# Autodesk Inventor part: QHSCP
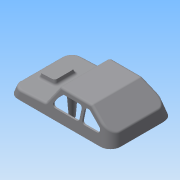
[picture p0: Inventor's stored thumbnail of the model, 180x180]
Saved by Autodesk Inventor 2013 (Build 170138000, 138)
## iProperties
Created: 2015-05
Part Number: QHSCP
Material: 일반
Document SubType Name: Modeling
Designer: WINDOWS7
Density: 1 g/cm^3
Author: WINDOWS7
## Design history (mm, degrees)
sketch "스케치1"
  geometry: L1 (0, 0)-(122, 0); L2 (122, 0)-(122, 76); L3 (122, 76)-(0, 76); L4 (0, 76)-(0, 0)
  constraints: 8 end point, 2 parallel, 1 horizontal, 1 perpendicular
  dimensions: "d1" = 122 distance of L1.start L1.end; "d2" = 76 distance of L3.end L1.start
extrude "돌출1" new body sketch "스케치1" distance "d3" = 9; taper "d4" = 0 deg
sketch "스케치2"
  geometry: L1 (0, 0)-(122, 0) reference; L2 (0, 9)-(122, 9) reference; L3 (0, 0)-(0, 9) reference; L4 (0, 9)-(42, 11.201); L5 (42, 11.201)-(54.372, 31); L6 (122, 0)-(118.412, 13.392); L7 (54.372, 31)-(92, 31); L8 (92, 31)-(122, 11); L9 (122, 0)-(122, 9) reference; L10 (119.588, 9)-(122, 9); L11 (122, 9)-(122, 0); 1 further point
  constraints: 14 end point, 4 point on line, 2 perpendicular, 1 collinear, 1 vertical alignment
  dimensions: "d5" = 3 deg angle of L2 L4; "d7" = 42 horizontal distance of L2.start L4.end; "d8" = 125 deg angle of L5 L4; "d9" = 31 distance from line of L1 L5.end; "d10" = 105 deg angle of L1 L6; "d11" = 30 horizontal distance of L7.end L1.end; "d13" = 20 distance from line of L7 point (122, 11); "d16" = 123.69 deg angle of L8 L9
extrude "돌출2" join sketch "스케치2" stored distance "d14" = 8; taper "d15" = 0 deg
extrude "돌출3" cut sketch "스케치2" stored distance "d17" = 8; taper "d18" = 0 deg
sketch "스케치3"
  geometry: L1 (0, 0)-(-122, 0) reference; L2 (0, 76)-(0, 0) reference; L3 (-122, 76)-(0, 76) reference; L4 (-122, 0)-(-122, 76) reference; L5 (-62.899, 88.126)-(-62.899, -13.455); L6 (-92, 76)-(-54.372, 76) reference
  constraints: 2 end point, 1 perpendicular
  dimensions: "d19" = 62.8987 distance between parallel lines of L2 L5; "d20" = 88.12563 distance from line of L5.start L1; "d21" = 13.45472 distance from line of L5.end L1
node "작업 평면1"
sketch "스케치4"
  geometry: L1 (104.027, 0)-(-0.312, 0); L2 (-0.312, 0)-(-0.312, -61.792); L3 (-0.312, -61.792)-(104.027, -61.792); L4 (104.027, -61.792)-(104.027, 0); L5 (88.126, 0)-(72.7, -57.568); L6 (72.7, -57.568)-(27.551, -57.568); L7 (12.126, 0)-(88.126, 0) reference; L8 (27.551, -57.568)-(12.126, 0)
  constraints: 14 end point, 3 parallel, 1 horizontal, 1 perpendicular
  dimensions: "d23" = 105 deg angle of L5 L1; "d24" = 105 deg angle of L1 L8; "d25" = 0 distance between parallel lines of L1 L7; "d26" = 61.79173 distance between parallel lines of L3 L7; "d27" = 57.56843 distance between parallel lines of L6 L7; "d28" = 104.3385 distance between parallel lines of L2 L4; "d29" = 15.90095 distance from line of L5.start L4
extrude "돌출4" cut sketch "스케치4" stored distance "d30" = 8; taper "d31" = 0 deg
sketch "스케치5"
  geometry: L1 (0, 0)-(-122, 0) reference; L2 (0, 76)-(0, 0) reference; L3 (-122, 76)-(0, 76) reference; L4 (-122, 0)-(-122, 76) reference; L5 (-122, 38)-(0, 38)
  constraints: 2 end point, 2 midpoint
node "작업 평면2"
sketch "스케치7"
  geometry: L1 (122, 0)-(119.554, -9.128); L2 (122, 0)-(0, 0) reference; L3 (122, -9)-(80, -11.201) reference; L4 (122, 0)-(119.554, 0); L5 (119.554, 0)-(119.554, -9.128); L6 (119.554, -9.128)-(122, -9.128); L7 (122, -9.128)-(122, 0)
  constraints: 10 end point, 2 parallel, 1 horizontal, 1 perpendicular, 1 point on line
  dimensions: "d40" = 105 deg angle of L1 L2
extrude "돌출6" cut sketch "스케치7" stored distance "d41" = 26; taper "d42" = 0 deg
sketch "스케치8"
  geometry: L1 (76, 0)-(0, 0) reference; L2 (8.306, 31)-(67.694, 31) reference; L3 (8.306, 31)-(67.694, 31) reference; C1 r 4 at (59, 0); C2 r 4 at (48, 0); C3 r 4 at (28, 0); C4 r 4 at (17, 0); 1 further point
  constraints: 4 centre point, 4 point on line, 3 equal radius, 1 midpoint
  dimensions: "d43" = 8 diameter of C1; "d45" = 11 distance of C4.centre C3.centre; "d46" = 11 distance of C2.centre C1.centre; "d47" = 20 distance of C3.centre C2.centre; "d48" = 10 horizontal distance of C2.centre point (38, 31)
extrude "돌출7" join sketch "스케치8" stored distance "d49" = 4; taper "d50" = 0 deg
sketch "스케치9"
  geometry: L1 (122, 0)-(0, 0) reference; L2 (114.644, 0)-(130.381, 0); L3 (130.381, 0)-(130.381, 5.483); L4 (130.381, 5.483)-(114.644, 5.483); L5 (114.644, 5.483)-(114.644, 0)
  constraints: 8 end point, 2 parallel, 1 horizontal, 1 perpendicular, 1 point on line
  dimensions: "d51" = 5.48259 distance between parallel lines of L4 L1; "d52" = 15.73649 distance between parallel lines of L3 L5; "d53" = 8.38057 distance from line of L1.start L3
extrude "돌출8" cut sketch "스케치9" stored distance "d54" = 4; taper "d55" = 0 deg
sketch "스케치10"
  geometry: L1 (74.23, -11)-(40.23, -11); L2 (40.23, -11)-(40.23, -26); L3 (40.23, -26)-(64.857, -26); L4 (64.857, -26)-(74.23, -11); L5 (30, -31)-(67.628, -31) reference; L6 (67.628, -31)-(80, -11.201) reference; L7 (3.588, -13.392)-(30, -31) reference; L8 (37.014, -26)-(37.014, -11); L9 (37.014, -11)-(9.014, -11); L10 (31.514, -26)-(9.014, -11); L11 (37.014, -26)-(31.514, -26); 1 further point
  constraints: 16 end point, 4 parallel, 3 perpendicular, 1 horizontal, 1 horizontal alignment
  dimensions: "d56" = 34 distance of L1.start L1.end; "d58" = 15 distance between parallel lines of L1 L3; "d59" = 5 distance between parallel lines of L5 L3; "d60" = 5 distance between parallel lines of L6 L4; "d63" = 28 distance of L8.end L9.end; "d64" = 5 distance between parallel lines of L7 L10; "d65" = 15 distance between parallel lines of L9 L11
extrude "돌출9" cut sketch "스케치10" stored distance "d66" = 4; taper "d67" = 0 deg
fillet "모깎기1" dims "d68" = 3
sketch "스케치12"
  geometry: L1 (-31.529, 48.734)-(-11.529, 48.734); L2 (-11.529, 48.734)-(-11.529, 22.734); L3 (-11.529, 22.734)-(-31.529, 22.734); L4 (-31.529, 22.734)-(-31.529, 48.734); L5 (-42.529, 40.999)-(-42.529, 28.999) reference; 1 further point
  constraints: 8 end point, 2 parallel, 1 horizontal, 1 perpendicular
  dimensions: "d81" = 26 distance of L3.end L1.start; "d83" = 20 distance between parallel lines of L2 L4; "d84" = 11 distance between parallel lines of L5 L4
extrude "돌출10" join sketch "스케치12" distance "d85" = 5; taper "d86" = -15 deg
sketch "스케치13"
  geometry: L1 (-11.529, 48.734)-(-11.529, 22.734) reference; L2 (-11.529, 22.734)-(-31.529, 22.734) reference; L3 (-31.529, 22.734)-(-31.529, 48.734) reference; L4 (-31.529, 48.734)-(-11.529, 48.734) reference; L5 (-29.529, 24.734)-(-13.529, 24.734); L6 (-13.529, 24.734)-(-13.529, 46.734); L7 (-13.529, 46.734)-(-29.529, 46.734); L8 (-29.529, 46.734)-(-29.529, 24.734); 1 further point
  constraints: 8 end point, 2 parallel, 1 horizontal, 1 perpendicular
  dimensions: "d87" = 2 distance between parallel lines of L3 L8; "d88" = 2 distance between parallel lines of L2 L5; "d89" = 2 distance between parallel lines of L7 L4; "d90" = 2 distance between parallel lines of L1 L6
extrude "돌출11" cut sketch "스케치13" distance "d91" = 3; taper "d92" = -15 deg
sketch "스케치14"
  geometry: L1 (-122, 76)-(0, 76) reference; L2 (-122, 0)-(-122, 76) reference; L3 (0, 0)-(-122, 0) reference; L4 (0, 13)-(0, 0) reference; L5 (-120, 74)-(-2, 74); L6 (-2, 74)-(-2, 2); L7 (-2, 2)-(-120, 2); L8 (-120, 2)-(-120, 74)
  constraints: 8 end point, 2 parallel, 1 horizontal, 1 perpendicular
  dimensions: "d93" = 2 distance between parallel lines of L1 L5; "d94" = 2 distance between parallel lines of L2 L8; "d95" = 2 distance between parallel lines of L3 L7; "d96" = 2 distance between parallel lines of L4 L6
extrude "돌출12" cut sketch "스케치14" distance "d97" = 7; taper "d98" = -15 deg
sketch "스케치16"
  geometry: L1 (32.422, -26)-(34.014, -26) reference; L2 (37.014, -23)-(37.014, -14) reference; L3 (34.014, -11)-(18.922, -11) reference; L4 (17.258, -16.496)-(30.758, -25.496) reference; L5 (65.738, -24.59)-(71.362, -15.59) reference; L6 (68.818, -11)-(43.23, -11) reference; L7 (40.23, -14)-(40.23, -23) reference; L8 (43.23, -26)-(63.194, -26) reference; L9 (122, 0)-(119.554, -9.128) reference; L10 (80, -11.201)-(119.554, -9.128) reference; L11 (67.628, -31)-(80, -11.201) reference; L12 (30, -31)-(67.628, -31) reference; L13 (3.588, -13.392)-(30, -31) reference; L14 (0, 0)-(3.588, -13.392) reference; L15 (0, 0)-(122, 0) reference; L16 (120, 0)-(118.124, -7) reference; A1 r 3 centre (34.014, -23) between (34.014, -26) and (37.014, -23) reference; A2 r 3 centre (34.014, -14) between (37.014, -14) and (34.014, -11) reference; A3 r 3 centre (18.922, -14) between (18.922, -11) and (17.258, -16.496) reference; A4 r 3 centre (32.422, -23) between (30.758, -25.496) and (32.422, -26) reference; A5 r 3 centre (68.818, -14) between (71.362, -15.59) and (68.818, -11) reference; A6 r 3 centre (43.23, -14) between (43.23, -11) and (40.23, -14) reference; A7 r 3 centre (43.23, -23) between (40.23, -23) and (43.23, -26) reference; A8 r 3 centre (63.194, -23) between (63.194, -26) and (65.738, -24.59) reference; 1 further point
  node "투영된 루프1"
sketch "스케치17"
  geometry: L1 (118.124, -7)-(78.985, -9.051); L2 (80, -11.201)-(119.554, -9.128) reference; L3 (67.628, -31)-(80, -11.201) reference; L4 (66.52, -29)-(30.606, -29); L5 (43.23, -26)-(63.194, -26) reference; L6 (30, -31)-(67.628, -31) reference; L7 (3.588, -13.392)-(30, -31) reference; L8 (30.606, -29)-(5.239, -12.089); L9 (5.239, -12.089)-(2, 0); L10 (2, 0)-(3.876, -7) reference; L11 (0, 0)-(3.588, -13.392) reference; L12 (66.52, -29)-(78.985, -9.051); L13 (118.124, -7)-(120, 0); L14 (120, 0)-(118.124, -7) reference; L15 (120, 0)-(2, 0); L16 (2, 0)-(120, 0) reference; 1 further point
  constraints: 14 end point, 6 parallel, 3 collinear, 1 point on line
  dimensions: "d100" = 2 distance between parallel lines of L6 L4; "d101" = 2 distance between parallel lines of L8 L7; "d102" = 2 distance between parallel lines of L12 L3
extrude "돌출13" cut sketch "스케치17" stored distance "d103" = 70; taper "d104" = 0 deg
extrude "돌출14" cut sketch "스케치17" stored distance "d105" = 70; taper "d106" = 0 deg
sketch "스케치19"
  geometry: L1 (-11.529, 48.734)-(-11.529, 22.734) reference; L2 (-11.529, 22.734)-(-31.529, 22.734) reference; L3 (-31.529, 22.734)-(-31.529, 48.734) reference; L4 (-31.529, 48.734)-(-11.529, 48.734) reference; L5 (-13.529, 24.734)-(-29.529, 24.734); L6 (-29.529, 24.734)-(-29.529, 46.734); L7 (-29.529, 46.734)-(-13.529, 46.734); L8 (-13.529, 46.734)-(-13.529, 24.734); 1 further point
  constraints: 8 end point, 2 parallel, 1 horizontal, 1 perpendicular
  dimensions: "d115" = 2 distance between parallel lines of L4 L7; "d116" = 2 distance between parallel lines of L1 L8; "d117" = 2 distance between parallel lines of L2 L5; "d118" = 2 distance between parallel lines of L3 L6
extrude "돌출15" cut sketch "스케치19" distance "d119" = 70; taper "d120" = 15 deg
sketch "스케치20"
  geometry: L1 (-120, 2)-(-120, 74) reference; L2 (-120, 74)-(-2, 74) reference; L3 (-2, 74)-(-2, 2) reference; L4 (-2, 2)-(-120, 2) reference; L5 (-122, 76)-(-118.412, 72.412) reference; L6 (-2.446, 2.446)-(0, 0) reference; L7 (-121, 75)-(-1.223, 75); L8 (-1.223, 75)-(-1.223, 1.223); L9 (-1.223, 1.223)-(-121, 1.223); L10 (-121, 1.223)-(-121, 75); L11 (-123.776, 77.776)-(3.96, 77.776); L12 (3.96, 77.776)-(3.96, -3.96); L13 (3.96, -3.96)-(-123.776, -3.96); L14 (-123.776, -3.96)-(-123.776, 77.776)
  constraints: 16 end point, 4 parallel, 2 horizontal, 2 perpendicular, 1 midpoint, 1 point on line
  dimensions: "d121" = 1 distance between parallel lines of L2 L7
extrude "돌출16" cut sketch "스케치20" distance "d122" = 1; taper "d123" = 0 deg
fillet "모깎기2" dims "d124" = 12
fillet "모깎기13" dims "d138" = 12
fillet "모깎기3" dims "d125" = 12
fillet "모깎기4" dims "d126" = 3
fillet "모깎기5" dims "d127" = 3
fillet "모깎기6" dims "d128" = 3
fillet "모깎기7" dims "d129" = 3
fillet "모깎기8" dims "d130" = 3
fillet "모깎기9" dims "d131" = 3
fillet "모깎기10" dims "d132" = 3
fillet "모깎기11" dims "d133" = 3
fillet "모깎기12" dims "d134" = 3
sketch "스케치22"
  geometry: L1 (121.732, 11.859)-(121.732, 64.141) reference; C1 r 3 at (100.732, 38); 2 further points
  constraints: 1 centre point, 1 horizontal alignment, 1 midpoint
  dimensions: "d139" = 21 distance from line of L1 C1.centre; "d140" = 6 diameter of C1
extrude "돌출17" join sketch "스케치22" stored distance "d141" = 1; taper "d142" = 4 deg
sketch "스케치23"
  geometry: L1 (121.732, 11.859)-(121.732, 64.141) reference; C1 r 3 at (60.732, 16); C2 r 3 at (60.732, 60); C3 r 3 at (100.732, 38) reference; 1 further point
  constraints: 2 centre point, 1 equal radius, 1 vertical alignment
  dimensions: "d143" = 61 distance from line of L1 C1.centre; "d144" = 6 diameter of C1; "d145" = 22 vertical distance of C3.centre C2.centre; "d146" = 44 distance of C1.centre C2.centre
extrude "돌출18" join sketch "스케치23" stored distance "d147" = 1; taper "d148" = 4 deg
sketch "스케치24"
  geometry: C1 r 3 at (20.732, 38); C2 r 3 at (60.732, 16) reference; C3 r 3 at (100.732, 38) reference; 1 further point
  constraints: 1 centre point, 1 horizontal alignment
  dimensions: "d149" = 40 horizontal distance of C2.centre C1.centre; "d150" = 6 diameter of C1
extrude "돌출19" join sketch "스케치24" stored distance "d151" = 10; taper "d152" = 4 deg
sketch "스케치25"
  geometry: C1 r 3 at (0, 0) reference; C2 r 3 at (40, 22) reference; C3 r 3 at (80, 0) reference; C4 r 3 at (40, -22) reference; 1 further point
hole "구멍1" sketch "스케치25" at (80, 0), (40, 22), (0, 0), (40, -22) diameter "d153" = 3.242; stored, may be unused: countersink angle "d157" = 90 deg, drill point angle "d159" = 118 deg; dims "d154" = 9, "d155" = 4, "d156" = 2, "d158" = 11
node "솔리드1"
node "투영된 루프3"
node "투영된 루프4"
node "투영된 루프5"
other parameters: "d22" = 90 deg, "d32" = 90 deg
